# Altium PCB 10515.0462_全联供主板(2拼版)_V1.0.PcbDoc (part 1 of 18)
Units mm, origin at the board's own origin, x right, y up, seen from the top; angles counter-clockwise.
Board outline 282 x 198 mm, 2 copper layers (Top Layer, Bottom Layer); 716 components, 0 nets, 2364 pads, 1800 vias.
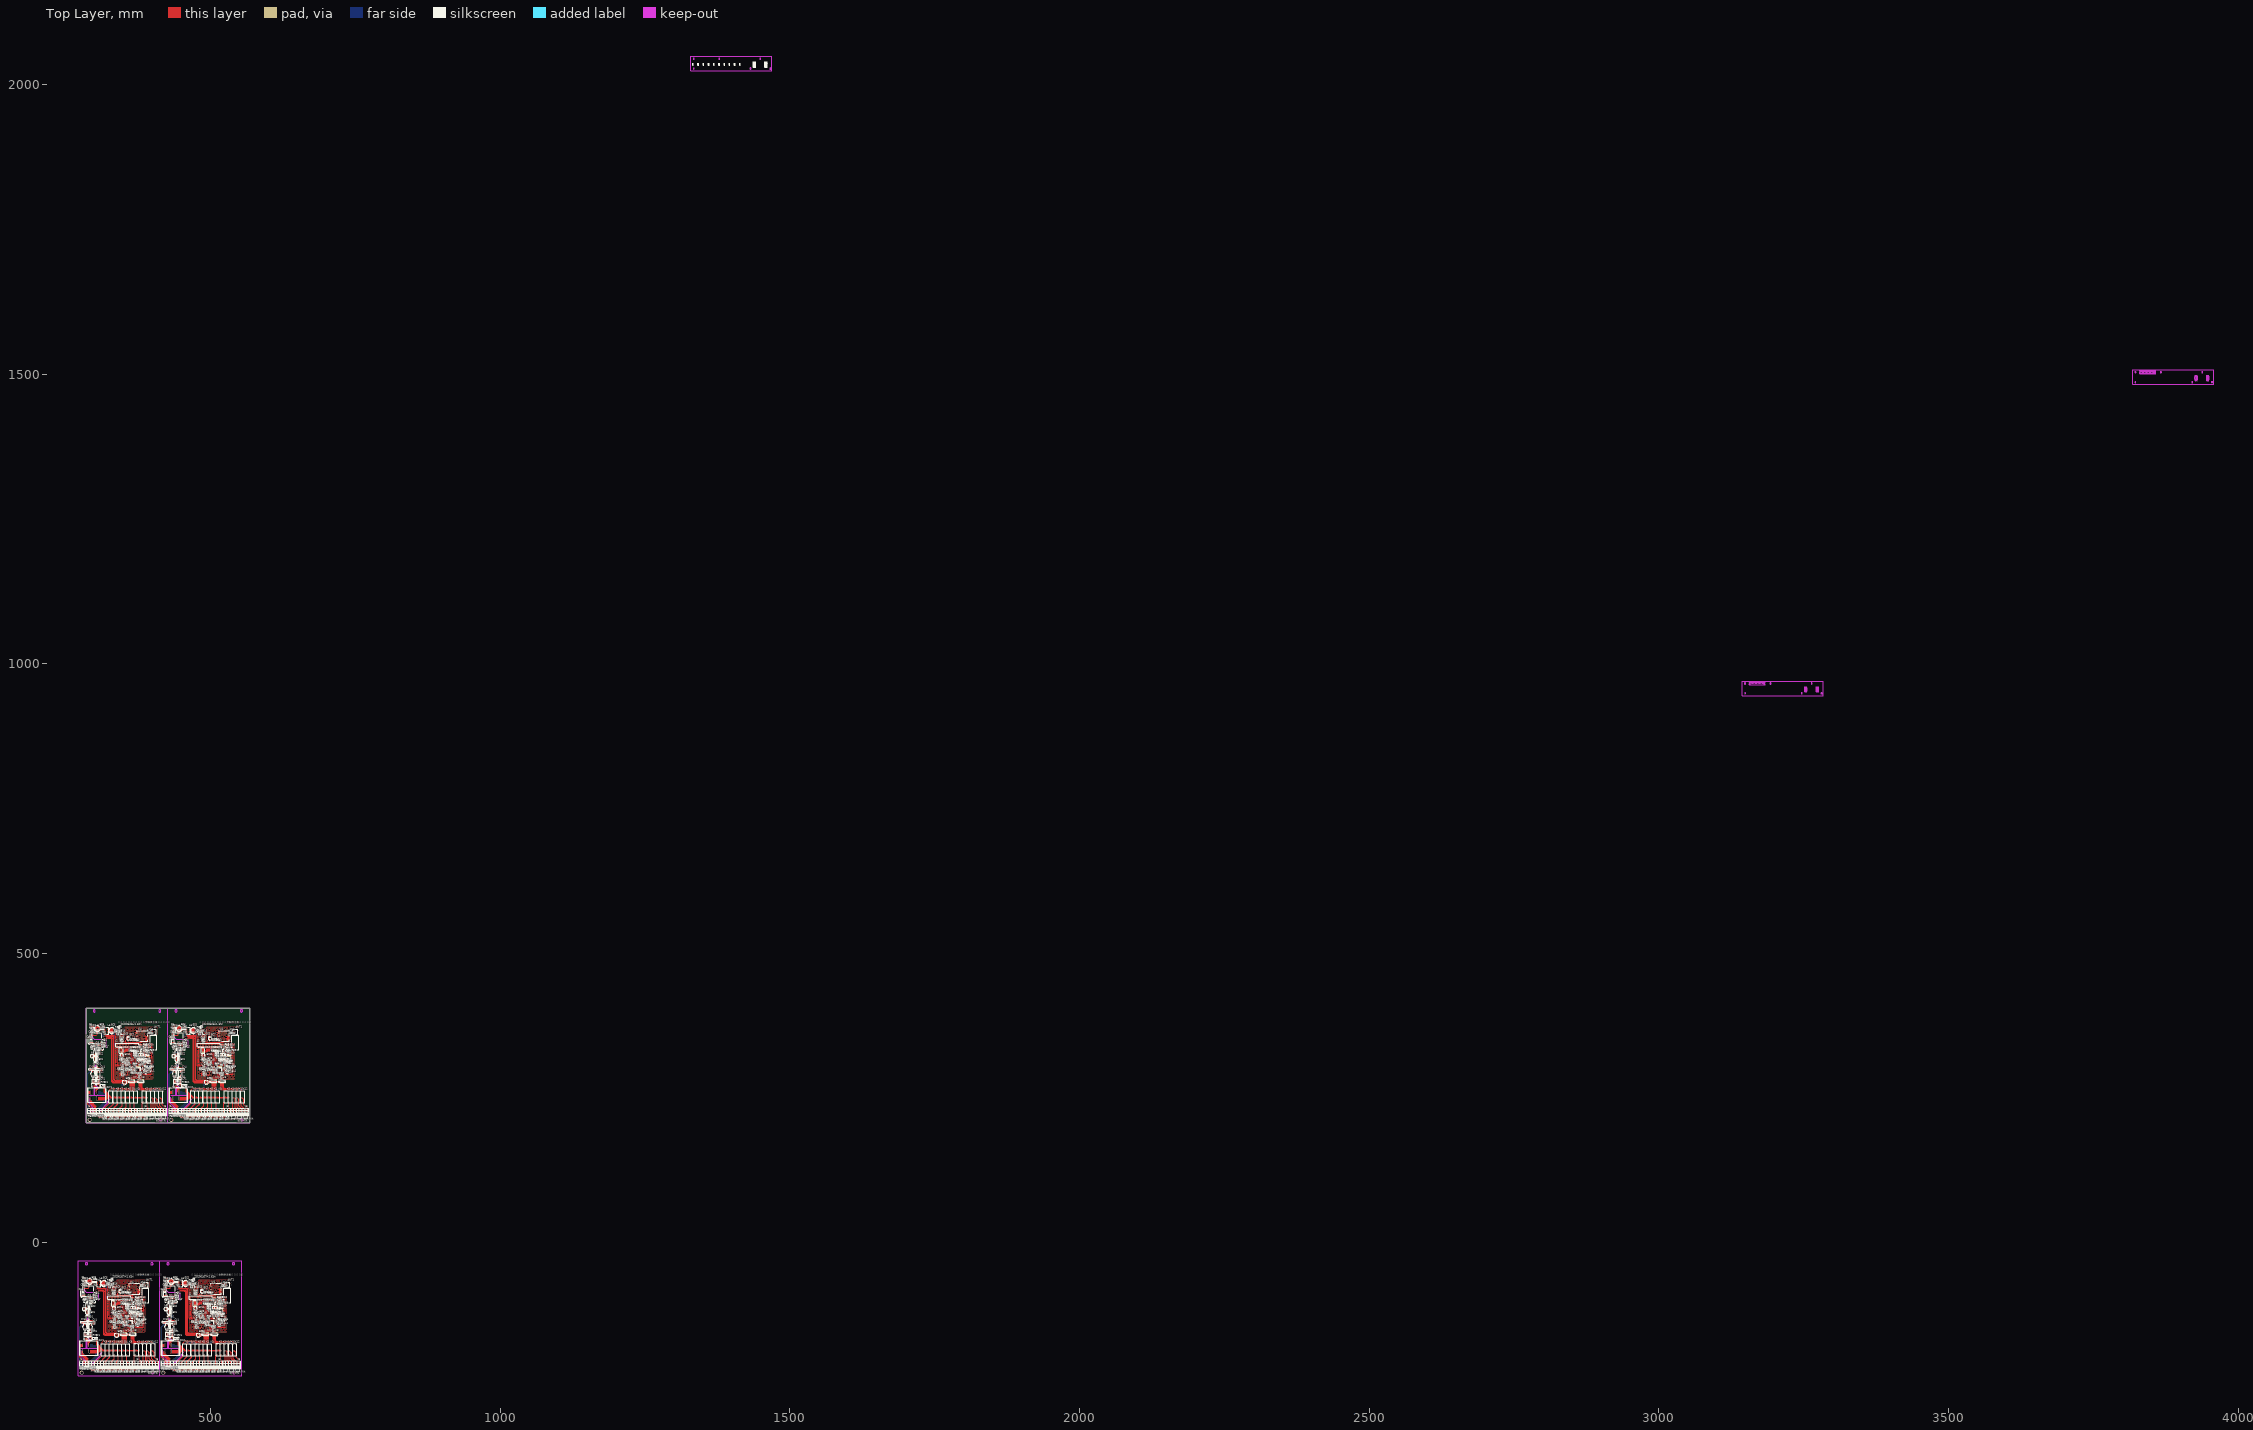
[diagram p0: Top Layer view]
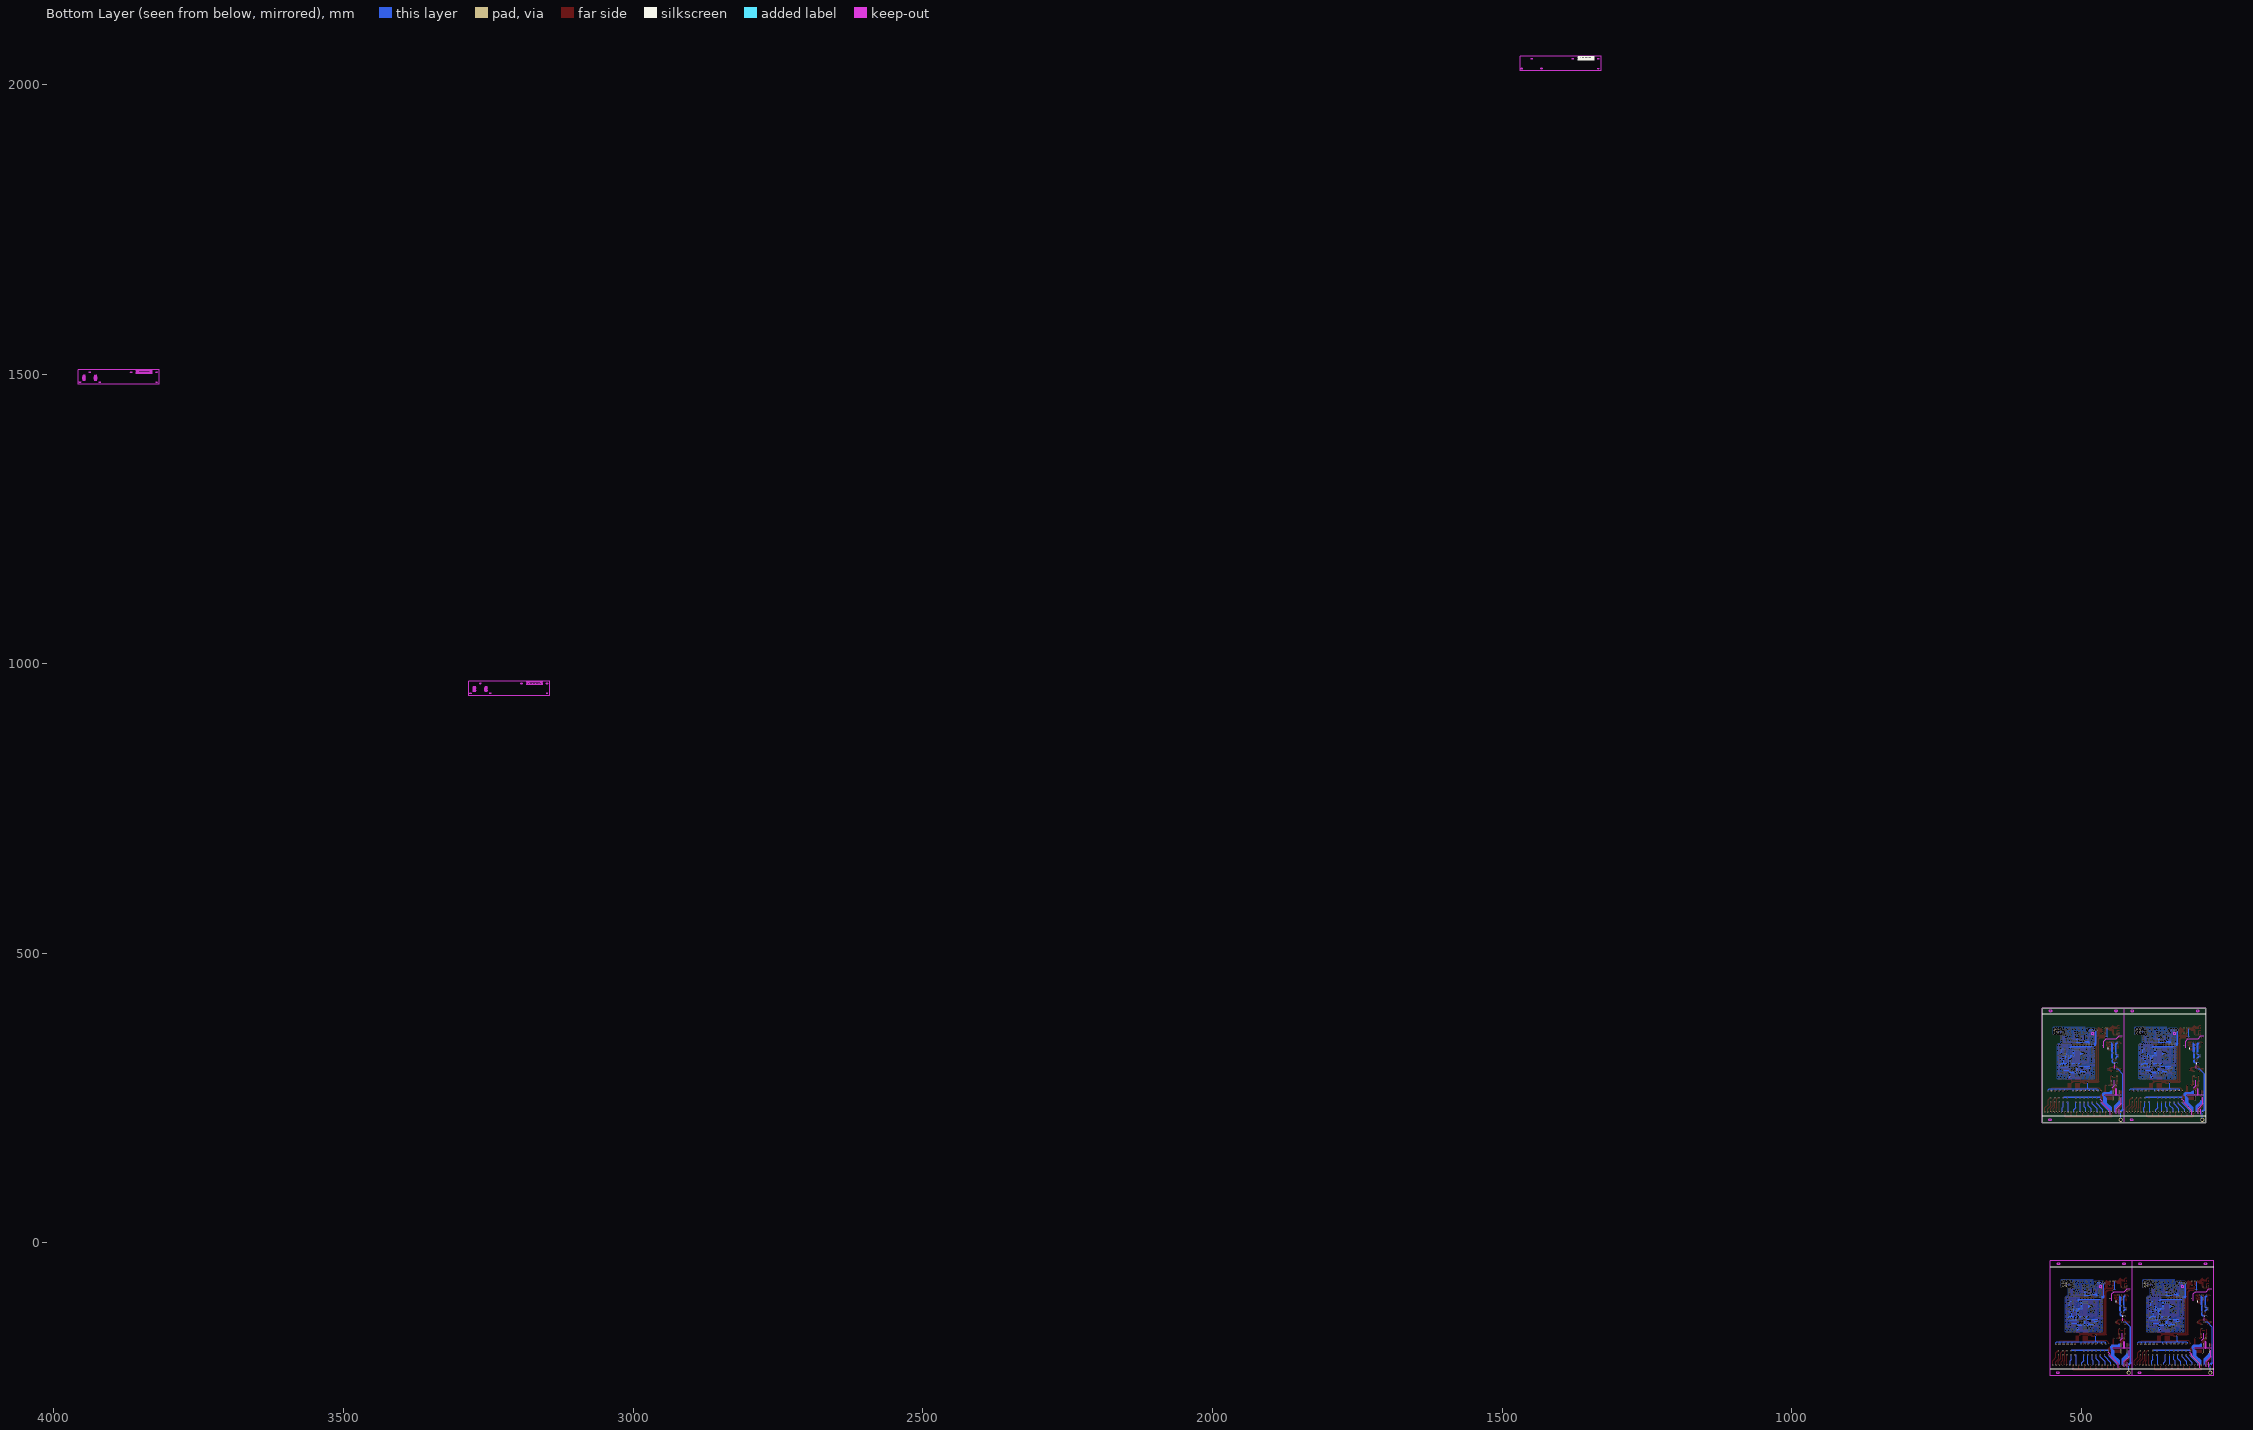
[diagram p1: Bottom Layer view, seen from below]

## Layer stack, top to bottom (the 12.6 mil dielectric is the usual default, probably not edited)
Top Layer: signal copper 0.0356
Dielectric: dielectric 0.32, FR-4, Dk 4.8
Bottom Layer: signal copper 0.0356

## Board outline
285.008,405.708 567.008,405.708 567.008,207.708 285.008,207.708 285.008,405.708

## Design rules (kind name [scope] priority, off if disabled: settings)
Clearance [All] p1: gap=0.254
PolygonConnect [All] p1: connectstyle=Relief reliefconductorwidth=0.254 reliefentries=4 polygonreliefangle="90 Angle"
RoutingVias [All] p1: holewidth=0.711 width=1.27 viastyle="Through Hole" minholewidth=0.711 minwidth=1.27 maxholewidth=0.711 maxwidth=1.27
SilkscreenOverComponentPads [All] p1: minsilkscreentomaskgap=0.254
SolderMaskExpansion [All] p1: expansion=0.102
Width [All] p1: maxlimit=0.254 minlimit=0.254 preferedwidth=0.254
27 further rules are at their usual default settings.

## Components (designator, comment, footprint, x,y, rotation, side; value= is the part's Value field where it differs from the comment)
+3.3V "OTHER/TEST" TEST#1 486.46,315.284 r90 top (schematic designator VCC1)
+3.3V "OTHER/TEST" TEST#1 345.46,315.284 r90 top (schematic designator VCC1)
+3.3V "OTHER/TEST" TEST#1 472.831,-121.311 r90 top (schematic designator VCC1)
+3.3V "OTHER/TEST" TEST#1 331.831,-121.311 r90 top (schematic designator VCC1)
ANT1 "SMA座" SMA 542.201,364.654 r180 top
ANT1 "SMA座" SMA 401.201,364.654 r180 top
ANT1 "SMA座" SMA 528.573,-71.942 r180 top
ANT1 "SMA座" SMA 387.573,-71.942 r180 top
C1 "1nF/630V" CAP/SMT/1206C 434.678,372.042 r90 top
C1 "1nF/630V" CAP/SMT/1206C 293.678,372.042 r90 top
C1 "1nF/630V" CAP/SMT/1206C 421.049,-64.553 r90 top
C1 "1nF/630V" CAP/SMT/1206C 280.049,-64.553 r90 top
C2 "1nF/630V" CAP/SMT/1206C 437.98,339.657 r90 top
C2 "1nF/630V" CAP/SMT/1206C 296.98,339.657 r90 top
C2 "1nF/630V" CAP/SMT/1206C 424.351,-96.938 r90 top
C2 "1nF/630V" CAP/SMT/1206C 283.351,-96.938 r90 top
C3 "1uF/0603" CAP/SMT/0603C 451.662,370.021 r270 top
C3 "1uF/0603" CAP/SMT/0603C 310.662,370.021 r270 top
C3 "1uF/0603" CAP/SMT/0603C 438.033,-66.574 r270 top
C3 "1uF/0603" CAP/SMT/0603C 297.033,-66.574 r270 top
C4 "0.1uF/0603" CAP/SMT/0603C 453.44,370.021 r270 top
C4 "0.1uF/0603" CAP/SMT/0603C 312.44,370.021 r270 top
C4 "0.1uF/0603" CAP/SMT/0603C 439.811,-66.574 r270 top
C4 "0.1uF/0603" CAP/SMT/0603C 298.811,-66.574 r270 top
C5 "0.1uF/0603" CAP/SMT/0603C 480.096,364.013 r180 top
C5 "0.1uF/0603" CAP/SMT/0603C 339.096,364.013 r180 top
C5 "0.1uF/0603" CAP/SMT/0603C 466.467,-72.582 r180 top
C5 "0.1uF/0603" CAP/SMT/0603C 325.467,-72.582 r180 top
C6 "0.1uF/0603" CAP/SMT/0603C 476.413,367.292 r270 top
C6 "0.1uF/0603" CAP/SMT/0603C 335.413,367.292 r270 top
C6 "0.1uF/0603" CAP/SMT/0603C 462.784,-69.303 r270 top
C6 "0.1uF/0603" CAP/SMT/0603C 321.784,-69.303 r270 top
C7 "0.1uF/0603" CAP/SMT/0603C 488.492,347.796 r180 top
C7 "0.1uF/0603" CAP/SMT/0603C 347.492,347.796 r180 top
C7 "0.1uF/0603" CAP/SMT/0603C 474.863,-88.799 r180 top
C7 "0.1uF/0603" CAP/SMT/0603C 333.863,-88.799 r180 top
C8 "1nF/0603" CAP/SMT/0603C 484.21,365.864 r90 top
C8 "1nF/0603" CAP/SMT/0603C 343.21,365.864 r90 top
C8 "1nF/0603" CAP/SMT/0603C 470.581,-70.731 r90 top
C8 "1nF/0603" CAP/SMT/0603C 329.581,-70.731 r90 top
C9 "10uF/0603" CAP/SMT/0603C 494.749,298.509 r90 top
C9 "10uF/0603" CAP/SMT/0603C 353.749,298.509 r90 top
C9 "10uF/0603" CAP/SMT/0603C 481.12,-138.086 r90 top
C9 "10uF/0603" CAP/SMT/0603C 340.12,-138.086 r90 top
C10 "0.1uF/0603" CAP/SMT/0603C 481.922,300.153 r90 top
C10 "0.1uF/0603" CAP/SMT/0603C 340.922,300.153 r90 top
C10 "0.1uF/0603" CAP/SMT/0603C 468.293,-136.442 r90 top
C10 "0.1uF/0603" CAP/SMT/0603C 327.293,-136.442 r90 top
C11 "0.1uF/0603" CAP/SMT/0603C 511.757,322.159 r180 top
C11 "0.1uF/0603" CAP/SMT/0603C 370.757,322.159 r180 top
C11 "0.1uF/0603" CAP/SMT/0603C 498.129,-114.437 r180 top
C11 "0.1uF/0603" CAP/SMT/0603C 357.128,-114.437 r180 top
C12 "1uF/0603" CAP/SMT/0603C 504.24,352.114 r270 top
C12 "1uF/0603" CAP/SMT/0603C 363.24,352.114 r270 top
C12 "1uF/0603" CAP/SMT/0603C 490.611,-84.481 r270 top
C12 "1uF/0603" CAP/SMT/0603C 349.611,-84.481 r270 top
C13 "0.1uF/0603" CAP/SMT/0603C 511.86,350.59 r90 top
C13 "0.1uF/0603" CAP/SMT/0603C 370.86,350.59 r90 top
C13 "0.1uF/0603" CAP/SMT/0603C 498.231,-86.005 r90 top
C13 "0.1uF/0603" CAP/SMT/0603C 357.231,-86.005 r90 top
C14 "0.1uF/0603" CAP/SMT/0603C 510.463,350.59 r90 top
C14 "0.1uF/0603" CAP/SMT/0603C 369.463,350.59 r90 top
C14 "0.1uF/0603" CAP/SMT/0603C 496.834,-86.005 r90 top
C14 "0.1uF/0603" CAP/SMT/0603C 355.834,-86.005 r90 top
C15 "1uF/0603" CAP/SMT/0603C 509.066,350.59 r90 top
C15 "1uF/0603" CAP/SMT/0603C 368.066,350.59 r90 top
C15 "1uF/0603" CAP/SMT/0603C 495.437,-86.005 r90 top
C15 "1uF/0603" CAP/SMT/0603C 354.437,-86.005 r90 top
C16 "0.1uF/0603" CAP/SMT/0603C 502.97,350.56 r90 top
C16 "0.1uF/0603" CAP/SMT/0603C 361.97,350.56 r90 top
C16 "0.1uF/0603" CAP/SMT/0603C 489.341,-86.036 r90 top
C16 "0.1uF/0603" CAP/SMT/0603C 348.341,-86.036 r90 top
C17 "NC" CAP/SMT/0603C 534.327,361.733 r90 top
C17 "NC" CAP/SMT/0603C 393.327,361.733 r90 top
C17 "NC" CAP/SMT/0603C 520.699,-74.863 r90 top
C17 "NC" CAP/SMT/0603C 379.699,-74.863 r90 top
C18 "NC" CAP/SMT/0603C 536.105,361.606 r90 top
C18 "NC" CAP/SMT/0603C 395.105,361.606 r90 top
C18 "NC" CAP/SMT/0603C 522.477,-74.99 r90 top
C18 "NC" CAP/SMT/0603C 381.477,-74.99 r90 top
C19 "0.1uF/0603" CAP/SMT/0603C 519.006,290.508 r0 top
C19 "0.1uF/0603" CAP/SMT/0603C 378.006,290.508 r0 top
C19 "0.1uF/0603" CAP/SMT/0603C 505.377,-146.087 r0 top
C19 "0.1uF/0603" CAP/SMT/0603C 364.377,-146.087 r0 top
C20 "0.1uF/0603" CAP/SMT/0603C 519.895,307.78 r180 top
C20 "0.1uF/0603" CAP/SMT/0603C 378.895,307.78 r180 top
C20 "0.1uF/0603" CAP/SMT/0603C 506.266,-128.815 r180 top
C20 "0.1uF/0603" CAP/SMT/0603C 365.266,-128.815 r180 top
C21 "0.1uF/0603" CAP/SMT/0603C 524.086,301.684 r90 top
C21 "0.1uF/0603" CAP/SMT/0603C 383.086,301.684 r90 top
C21 "0.1uF/0603" CAP/SMT/0603C 510.457,-134.911 r90 top
C21 "0.1uF/0603" CAP/SMT/0603C 369.457,-134.911 r90 top
C22 "0.1uF/0603" CAP/SMT/0603C 506.306,295.08 r270 top
C22 "0.1uF/0603" CAP/SMT/0603C 365.306,295.08 r270 top
C22 "0.1uF/0603" CAP/SMT/0603C 492.677,-141.515 r270 top
C22 "0.1uF/0603" CAP/SMT/0603C 351.677,-141.515 r270 top
C23 "0.1uF/0603" CAP/SMT/0603C 488.17,295.03 r0 top
C23 "0.1uF/0603" CAP/SMT/0603C 347.17,295.03 r0 top
C23 "0.1uF/0603" CAP/SMT/0603C 474.541,-141.565 r0 top
C23 "0.1uF/0603" CAP/SMT/0603C 333.541,-141.565 r0 top
C24 "0.1uF/0603" CAP/SMT/0603C 528.905,302.897 r0 top
C24 "0.1uF/0603" CAP/SMT/0603C 387.905,302.897 r0 top
C24 "0.1uF/0603" CAP/SMT/0603C 515.276,-133.698 r0 top
C24 "0.1uF/0603" CAP/SMT/0603C 374.276,-133.698 r0 top
C25 "20pF/0603" CAP/SMT/0603C 529.777,293.375 r180 top
C25 "20pF/0603" CAP/SMT/0603C 388.777,293.375 r180 top
C25 "20pF/0603" CAP/SMT/0603C 516.148,-143.22 r180 top
C25 "20pF/0603" CAP/SMT/0603C 375.148,-143.22 r180 top
C26 "20pF/0603" CAP/SMT/0603C 528.474,299.532 r0 top
C26 "20pF/0603" CAP/SMT/0603C 387.474,299.532 r0 top
C26 "20pF/0603" CAP/SMT/0603C 514.845,-137.063 r0 top
C26 "20pF/0603" CAP/SMT/0603C 373.845,-137.063 r0 top
C27 "0.1uF/0603" CAP/SMT/0603C 511.386,306.891 r180 top
C27 "0.1uF/0603" CAP/SMT/0603C 370.386,306.891 r180 top
C27 "0.1uF/0603" CAP/SMT/0603C 497.757,-129.704 r180 top
C27 "0.1uF/0603" CAP/SMT/0603C 356.757,-129.704 r180 top
C28 "0.1uF/0603" CAP/SMT/0603C 502.72,334.704 r180 top
C28 "0.1uF/0603" CAP/SMT/0603C 361.72,334.704 r180 top
C28 "0.1uF/0603" CAP/SMT/0603C 489.091,-101.891 r180 top
C28 "0.1uF/0603" CAP/SMT/0603C 348.091,-101.891 r180 top
C29 "0.1uF/0603" CAP/SMT/0603C 492.556,312.236 r270 top
C29 "0.1uF/0603" CAP/SMT/0603C 351.556,312.236 r270 top
C29 "0.1uF/0603" CAP/SMT/0603C 478.927,-124.359 r270 top
C29 "0.1uF/0603" CAP/SMT/0603C 337.927,-124.359 r270 top
C30 "0.1uF/0603" CAP/SMT/0603C 506.235,334.704 r180 top
C30 "0.1uF/0603" CAP/SMT/0603C 365.235,334.704 r180 top
C30 "0.1uF/0603" CAP/SMT/0603C 492.607,-101.891 r180 top
C30 "0.1uF/0603" CAP/SMT/0603C 351.607,-101.891 r180 top
C31 "0.1uF/0603" CAP/SMT/0603C 488.492,313.252 r180 top
C31 "0.1uF/0603" CAP/SMT/0603C 347.492,313.252 r180 top
C31 "0.1uF/0603" CAP/SMT/0603C 474.863,-123.343 r180 top
C31 "0.1uF/0603" CAP/SMT/0603C 333.863,-123.343 r180 top
C32 "0.1uF/0603" CAP/SMT/0603C 509.705,334.704 r180 top
C32 "0.1uF/0603" CAP/SMT/0603C 368.705,334.704 r180 top
C32 "0.1uF/0603" CAP/SMT/0603C 496.076,-101.891 r180 top
C32 "0.1uF/0603" CAP/SMT/0603C 355.076,-101.891 r180 top
C34 "51pF" CAP/SMT/0603C 513.783,323.742 r0 top
C34 "51pF" CAP/SMT/0603C 372.783,323.742 r0 top
C34 "51pF" CAP/SMT/0603C 500.154,-112.853 r0 top
C34 "51pF" CAP/SMT/0603C 359.154,-112.853 r0 top
C35 "0.1uF/0603" CAP/SMT/0603C 499.067,279.586 r270 top
C35 "0.1uF/0603" CAP/SMT/0603C 358.067,279.586 r270 top
C35 "0.1uF/0603" CAP/SMT/0603C 485.438,-157.009 r270 top
C35 "0.1uF/0603" CAP/SMT/0603C 344.438,-157.009 r270 top
C36 "0.1uF/0603" CAP/SMT/0603C 514.561,279.586 r270 top
C36 "0.1uF/0603" CAP/SMT/0603C 373.561,279.586 r270 top
C36 "0.1uF/0603" CAP/SMT/0603C 500.932,-157.009 r270 top
C36 "0.1uF/0603" CAP/SMT/0603C 359.932,-157.009 r270 top
C37 "0.1uF/0603" CAP/SMT/0603C 529.132,324.564 r90 top
C37 "0.1uF/0603" CAP/SMT/0603C 388.132,324.564 r90 top
C37 "0.1uF/0603" CAP/SMT/0603C 515.503,-112.032 r90 top
C37 "0.1uF/0603" CAP/SMT/0603C 374.503,-112.032 r90 top
C40 "1uF/0603" CAP/SMT/0603C 500.557,312.236 r270 top
C40 "1uF/0603" CAP/SMT/0603C 359.557,312.236 r270 top
C40 "1uF/0603" CAP/SMT/0603C 486.928,-124.359 r270 top
C40 "1uF/0603" CAP/SMT/0603C 345.928,-124.359 r270 top
C42 "22uF/0805" CAP/SMT/0805C 489,349.828 r180 top
C42 "22uF/0805" CAP/SMT/0805C 348,349.828 r180 top
C42 "22uF/0805" CAP/SMT/0805C 475.371,-86.767 r180 top
C42 "22uF/0805" CAP/SMT/0805C 334.371,-86.767 r180 top
C43 "22uF/0805" CAP/SMT/0805C 489,352.368 r180 top
C43 "22uF/0805" CAP/SMT/0805C 348,352.368 r180 top
C43 "22uF/0805" CAP/SMT/0805C 475.371,-84.227 r180 top
C43 "22uF/0805" CAP/SMT/0805C 334.371,-84.227 r180 top
C44 "0.1uF/0603" CAP/SMT/0603C 488.492,346.272 r180 top
C44 "0.1uF/0603" CAP/SMT/0603C 347.492,346.272 r180 top
C44 "0.1uF/0603" CAP/SMT/0603C 474.863,-90.323 r180 top
C44 "0.1uF/0603" CAP/SMT/0603C 333.863,-90.323 r180 top
C45 "0.1uF/0603" CAP/SMT/0603C 511.352,308.299 r180 top
C45 "0.1uF/0603" CAP/SMT/0603C 370.352,308.299 r180 top
C45 "0.1uF/0603" CAP/SMT/0603C 497.723,-128.296 r180 top
C45 "0.1uF/0603" CAP/SMT/0603C 356.723,-128.296 r180 top
C46 "0.1uF/0603" CAP/SMT/0603C 488.492,317.316 r180 top
C46 "0.1uF/0603" CAP/SMT/0603C 347.492,317.316 r180 top
C46 "0.1uF/0603" CAP/SMT/0603C 474.863,-119.279 r180 top
C46 "0.1uF/0603" CAP/SMT/0603C 333.863,-119.279 r180 top
C48 "0.1uF/0603" CAP/SMT/0603C 488.145,305.621 r0 top
C48 "0.1uF/0603" CAP/SMT/0603C 347.145,305.621 r0 top
C48 "0.1uF/0603" CAP/SMT/0603C 474.516,-130.974 r0 top
C48 "0.1uF/0603" CAP/SMT/0603C 333.516,-130.974 r0 top
C49 "10uF/0603" CAP/SMT/0603C 499.321,298.509 r90 top
C49 "10uF/0603" CAP/SMT/0603C 358.321,298.509 r90 top
C49 "10uF/0603" CAP/SMT/0603C 485.692,-138.086 r90 top
C49 "10uF/0603" CAP/SMT/0603C 344.692,-138.086 r90 top
CX1 "NC" CAP/DIP/0.1uF/250V 438.2,279.724 r180 top
CX1 "NC" CAP/DIP/0.1uF/250V 297.2,279.724 r180 top
CX1 "NC" CAP/DIP/0.1uF/250V 424.571,-156.871 r180 top
CX1 "NC" CAP/DIP/0.1uF/250V 283.571,-156.871 r180 top
CY1 "222M/250V" CAP/DIP/102M/250V 431.249,344.61 r90 top
CY1 "222M/250V" CAP/DIP/102M/250V 290.249,344.61 r90 top
CY1 "222M/250V" CAP/DIP/102M/250V 417.62,-91.985 r90 top
CY1 "222M/250V" CAP/DIP/102M/250V 276.62,-91.985 r90 top
CY2 "222M/250V" CAP/DIP/102M/250V 434.678,352.611 r90 top
CY2 "222M/250V" CAP/DIP/102M/250V 293.678,352.611 r90 top
CY2 "222M/250V" CAP/DIP/102M/250V 421.049,-83.984 r90 top
CY2 "222M/250V" CAP/DIP/102M/250V 280.049,-83.984 r90 top
CY3 "NC" CAP/DIP/102M/250V 440.74,300.044 r180 top
CY3 "NC" CAP/DIP/102M/250V 299.74,300.044 r180 top
CY3 "NC" CAP/DIP/102M/250V 427.111,-136.551 r180 top
CY3 "NC" CAP/DIP/102M/250V 286.111,-136.551 r180 top
CY4 "NC" CAP/DIP/102M/250V 453.948,300.044 r180 top
CY4 "NC" CAP/DIP/102M/250V 312.948,300.044 r180 top
CY4 "NC" CAP/DIP/102M/250V 440.319,-136.551 r180 top
CY4 "NC" CAP/DIP/102M/250V 299.319,-136.551 r180 top
D1 "MB10S" D/SMT/MD6S-TR 442.298,307.653 r90 top
D1 "MB10S" D/SMT/MD6S-TR 301.298,307.653 r90 top
D1 "MB10S" D/SMT/MD6S-TR 428.669,-128.942 r90 top
D1 "MB10S" D/SMT/MD6S-TR 287.669,-128.942 r90 top
D2 "SS210" D/SMT/DO-214AC 438.234,366.073 r270 top
D2 "SS210" D/SMT/DO-214AC 297.234,366.073 r270 top
D2 "SS210" D/SMT/DO-214AC 424.605,-70.522 r270 top
D2 "SS210" D/SMT/DO-214AC 283.605,-70.522 r270 top
D3 "1N4007-SOD123" D/SMT/SOD123 440.647,338.514 r90 top
D3 "1N4007-SOD123" D/SMT/SOD123 299.647,338.514 r90 top
D3 "1N4007-SOD123" D/SMT/SOD123 427.018,-98.081 r90 top
D3 "1N4007-SOD123" D/SMT/SOD123 286.018,-98.081 r90 top
D4 "F7" D/SMT/DO-214AC 456.996,346.272 r90 top
D4 "F7" D/SMT/DO-214AC 315.996,346.272 r90 top
D4 "F7" D/SMT/DO-214AC 443.367,-90.323 r90 top
D4 "F7" D/SMT/DO-214AC 302.367,-90.323 r90 top
D5 "1N4148/SOD-123" D/SMT/SOD-123 534.112,302.897 r180 top
D5 "1N4148/SOD-123" D/SMT/SOD-123 393.112,302.897 r180 top
D5 "1N4148/SOD-123" D/SMT/SOD-123 520.483,-133.698 r180 top
D5 "1N4148/SOD-123" D/SMT/SOD-123 379.483,-133.698 r180 top
D6 "SMAJ13CA" D/SMT/SMBJ4.0A 513.892,333.191 r0 top
D6 "SMAJ13CA" D/SMT/SMBJ4.0A 372.892,333.191 r0 top
D6 "SMAJ13CA" D/SMT/SMBJ4.0A 500.263,-103.404 r0 top
D6 "SMAJ13CA" D/SMT/SMBJ4.0A 359.263,-103.404 r0 top
D9 "SMBJ6.5A/SOCAY" D/SMT/SMBJ4.0A 529.64,333.572 r90 top
D9 "SMBJ6.5A/SOCAY" D/SMT/SMBJ4.0A 388.64,333.572 r90 top
D9 "SMBJ6.5A/SOCAY" D/SMT/SMBJ4.0A 516.011,-103.023 r90 top
D9 "SMBJ6.5A/SOCAY" D/SMT/SMBJ4.0A 375.011,-103.023 r90 top
D10 "SMBJ6.5A/SOCAY" D/SMT/SMBJ4.0A 534.466,333.572 r90 top
D10 "SMBJ6.5A/SOCAY" D/SMT/SMBJ4.0A 393.466,333.572 r90 top
D10 "SMBJ6.5A/SOCAY" D/SMT/SMBJ4.0A 520.837,-103.023 r90 top
D10 "SMBJ6.5A/SOCAY" D/SMT/SMBJ4.0A 379.837,-103.023 r90 top
EC1 "8.2uF/400V" CAP/DIP/6.8UF/400V/10MM 442.806,317.686 r270 top
EC1 "8.2uF/400V" CAP/DIP/6.8UF/400V/10MM 301.806,317.686 r270 top
EC1 "8.2uF/400V" CAP/DIP/6.8UF/400V/10MM 429.177,-118.909 r270 top
EC1 "8.2uF/400V" CAP/DIP/6.8UF/400V/10MM 288.177,-118.909 r270 top
EC2 "8.2uF/400V" CAP/DIP/6.8UF/400V/10MM 442.806,327.973 r270 top
EC2 "8.2uF/400V" CAP/DIP/6.8UF/400V/10MM 301.806,327.973 r270 top
EC2 "8.2uF/400V" CAP/DIP/6.8UF/400V/10MM 429.177,-108.622 r270 top
EC2 "8.2uF/400V" CAP/DIP/6.8UF/400V/10MM 288.177,-108.622 r270 top
EC3 "330uF/50V" CAP/SMT/220UF/50V 450.519,375.228 r270 top
EC3 "330uF/50V" CAP/SMT/220UF/50V 309.519,375.228 r270 top
EC3 "330uF/50V" CAP/SMT/220UF/50V 436.89,-61.367 r270 top
EC3 "330uF/50V" CAP/SMT/220UF/50V 295.89,-61.367 r270 top
EC4 "10uF/50V" CAP/DIP/10uF/50V 453.855,336.609 r270 top
EC4 "10uF/50V" CAP/DIP/10uF/50V 312.855,336.609 r270 top
EC4 "10uF/50V" CAP/DIP/10uF/50V 440.226,-99.986 r270 top
EC4 "10uF/50V" CAP/DIP/10uF/50V 299.226,-99.986 r270 top
EC5 "220uF/50V" CAP/SMT/220UF/50V 475.284,371.672 r270 top
EC5 "220uF/50V" CAP/SMT/220UF/50V 334.284,371.672 r270 top
EC5 "220uF/50V" CAP/SMT/220UF/50V 461.655,-64.923 r270 top
EC5 "220uF/50V" CAP/SMT/220UF/50V 320.655,-64.923 r270 top
EC6 "220uF/16V" CAP/SMT/220UF/16V 487.476,357.448 r0 top
EC6 "220uF/16V" CAP/SMT/220UF/16V 346.476,357.448 r0 top
EC6 "220uF/16V" CAP/SMT/220UF/16V 473.847,-79.147 r0 top
EC6 "220uF/16V" CAP/SMT/220UF/16V 332.847,-79.147 r0 top
EC7 "330uF/6.3V" CAP/SMT/330UF/6.3V 498.652,349.828 r90 top
EC7 "330uF/6.3V" CAP/SMT/330UF/6.3V 357.652,349.828 r90 top
EC7 "330uF/6.3V" CAP/SMT/330UF/6.3V 485.023,-86.767 r90 top
EC7 "330uF/6.3V" CAP/SMT/330UF/6.3V 344.023,-86.767 r90 top
EC8 "100uF/50V" CAP/SMT/220UF/16V 492.556,277.438 r90 top
EC8 "100uF/50V" CAP/SMT/220UF/16V 351.556,277.438 r90 top
EC8 "100uF/50V" CAP/SMT/220UF/16V 478.927,-159.157 r90 top
EC8 "100uF/50V" CAP/SMT/220UF/16V 337.927,-159.157 r90 top
EC9 "TEC/47uF/10V" CAP/SMT/TAJC476M010RNJ 496.62,308.68 r90 top
EC9 "TEC/47uF/10V" CAP/SMT/TAJC476M010RNJ 355.62,308.68 r90 top
EC9 "TEC/47uF/10V" CAP/SMT/TAJC476M010RNJ 482.991,-127.915 r90 top
EC9 "TEC/47uF/10V" CAP/SMT/TAJC476M010RNJ 341.991,-127.915 r90 top
EC11 "100uF/25V" CAP/SMT/100UF/25V 484.428,323.92 r0 top
EC11 "100uF/25V" CAP/SMT/100UF/25V 343.428,323.92 r0 top
EC11 "100uF/25V" CAP/SMT/100UF/25V 470.799,-112.675 r0 top
EC11 "100uF/25V" CAP/SMT/100UF/25V 329.799,-112.675 r0 top
GND1 "OTHER/TEST" TEST#1 490.524,312.262 r270 top
GND1 "OTHER/TEST" TEST#1 349.524,312.262 r270 top
GND1 "OTHER/TEST" TEST#1 476.895,-124.334 r270 top
GND1 "OTHER/TEST" TEST#1 335.895,-124.334 r270 top
J1 "WJ103-5.0" CON/DIP/1×3PIN/5.0MM/WJ103-3P 436.71,225.611 r180 top
J1 "WJ103-5.0" CON/DIP/1×3PIN/5.0MM/WJ103-3P 295.71,225.611 r180 top
J1 "WJ103-5.0" CON/DIP/1×3PIN/5.0MM/WJ103-3P 423.081,-210.984 r180 top
J1 "WJ103-5.0" CON/DIP/1×3PIN/5.0MM/WJ103-3P 282.081,-210.984 r180 top
J2 "CON/DIP/2X15PIN" CON/DIP/2X15PIN/2.54MM 479.21,340.8 r90 top
J2 "CON/DIP/2X15PIN" CON/DIP/2X15PIN/2.54MM 338.21,340.8 r90 top
J2 "CON/DIP/2X15PIN" CON/DIP/2X15PIN/2.54MM 465.581,-95.795 r90 top
J2 "CON/DIP/2X15PIN" CON/DIP/2X15PIN/2.54MM 324.581,-95.795 r90 top
J3 "1X5PIN_2MM" CON/DIP/1×5PIN/2.0MM 536.144,305.437 r180 top
J3 "1X5PIN_2MM" CON/DIP/1×5PIN/2.0MM 395.144,305.437 r180 top
J3 "1X5PIN_2MM" CON/DIP/1×5PIN/2.0MM 522.515,-131.158 r180 top
J3 "1X5PIN_2MM" CON/DIP/1×5PIN/2.0MM 381.515,-131.158 r180 top
J6 "WJ103-5.0" CON/DIP/1×18PIN/5.0MM/WJ103-18P 492.59,225.611 r180 top
J6 "WJ103-5.0" CON/DIP/1×18PIN/5.0MM/WJ103-18P 351.59,225.611 r180 top
J6 "WJ103-5.0" CON/DIP/1×18PIN/5.0MM/WJ103-18P 478.961,-210.984 r180 top
J6 "WJ103-5.0" CON/DIP/1×18PIN/5.0MM/WJ103-18P 337.961,-210.984 r180 top
J8 "WJ103-5.0" CON/DIP/1×6PIN/5.0MM/WJ103-6P 550.092,225.611 r180 top
J8 "WJ103-5.0" CON/DIP/1×6PIN/5.0MM/WJ103-6P 409.092,225.611 r180 top
J8 "WJ103-5.0" CON/DIP/1×6PIN/5.0MM/WJ103-6P 536.463,-210.984 r180 top
J8 "WJ103-5.0" CON/DIP/1×6PIN/5.0MM/WJ103-6P 395.463,-210.984 r180 top
K1 "HF46F/024-HS1T" RELAY/HF46F-012-HSIT 535.897,261.97 r0 top
K1 "HF46F/024-HS1T" RELAY/HF46F-012-HSIT 394.897,261.97 r0 top
K1 "HF46F/024-HS1T" RELAY/HF46F-012-HSIT 522.268,-174.625 r0 top
K1 "HF46F/024-HS1T" RELAY/HF46F-012-HSIT 381.268,-174.625 r0 top
K2 "HF46F/024-HS1T" RELAY/HF46F-012-HSIT 528.785,261.97 r0 top
K2 "HF46F/024-HS1T" RELAY/HF46F-012-HSIT 387.785,261.97 r0 top
K2 "HF46F/024-HS1T" RELAY/HF46F-012-HSIT 515.156,-174.625 r0 top
K2 "HF46F/024-HS1T" RELAY/HF46F-012-HSIT 374.156,-174.625 r0 top
K3 "HF46F/024-HS1T" RELAY/HF46F-012-HSIT 513.926,261.843 r0 top
K3 "HF46F/024-HS1T" RELAY/HF46F-012-HSIT 372.926,261.843 r0 top
K3 "HF46F/024-HS1T" RELAY/HF46F-012-HSIT 500.297,-174.752 r0 top
K3 "HF46F/024-HS1T" RELAY/HF46F-012-HSIT 359.297,-174.752 r0 top
K4 "HF46F/024-HS1T" RELAY/HF46F-012-HSIT 506.824,261.843 r0 top
K4 "HF46F/024-HS1T" RELAY/HF46F-012-HSIT 365.823,261.843 r0 top
K4 "HF46F/024-HS1T" RELAY/HF46F-012-HSIT 493.195,-174.752 r0 top
K4 "HF46F/024-HS1T" RELAY/HF46F-012-HSIT 352.195,-174.752 r0 top
K5 "HF46F/024-HS1T" RELAY/HF46F-012-HSIT 499.664,261.843 r0 top
K5 "HF46F/024-HS1T" RELAY/HF46F-012-HSIT 358.664,261.843 r0 top
K5 "HF46F/024-HS1T" RELAY/HF46F-012-HSIT 486.035,-174.752 r0 top
K5 "HF46F/024-HS1T" RELAY/HF46F-012-HSIT 345.035,-174.752 r0 top
K6 "HF46F/024-HS1T" RELAY/HF46F-012-HSIT 492.504,261.843 r0 top
K6 "HF46F/024-HS1T" RELAY/HF46F-012-HSIT 351.504,261.843 r0 top
K6 "HF46F/024-HS1T" RELAY/HF46F-012-HSIT 478.875,-174.752 r0 top
K6 "HF46F/024-HS1T" RELAY/HF46F-012-HSIT 337.875,-174.752 r0 top
K7 "HF46F/024-HS1T" RELAY/HF46F-012-HSIT 485.345,261.843 r0 top
K7 "HF46F/024-HS1T" RELAY/HF46F-012-HSIT 344.345,261.843 r0 top
K7 "HF46F/024-HS1T" RELAY/HF46F-012-HSIT 471.716,-174.752 r0 top
K7 "HF46F/024-HS1T" RELAY/HF46F-012-HSIT 330.716,-174.752 r0 top
K8 "HF46F/024-HS1T" RELAY/HF46F-012-HSIT 478.185,261.843 r0 top
K8 "HF46F/024-HS1T" RELAY/HF46F-012-HSIT 337.185,261.843 r0 top
K8 "HF46F/024-HS1T" RELAY/HF46F-012-HSIT 464.556,-174.752 r0 top
K8 "HF46F/024-HS1T" RELAY/HF46F-012-HSIT 323.556,-174.752 r0 top
K9 "HF46F/024-HS1T" RELAY/HF46F-012-HSIT 471,261.843 r0 top
K9 "HF46F/024-HS1T" RELAY/HF46F-012-HSIT 330,261.843 r0 top
K9 "HF46F/024-HS1T" RELAY/HF46F-012-HSIT 457.371,-174.752 r0 top
K9 "HF46F/024-HS1T" RELAY/HF46F-012-HSIT 316.371,-174.752 r0 top
K10 "HF46F/024-HS1T" RELAY/HF46F-012-HSIT 543.016,261.97 r0 top
K10 "HF46F/024-HS1T" RELAY/HF46F-012-HSIT 402.016,261.97 r0 top
K10 "HF46F/024-HS1T" RELAY/HF46F-012-HSIT 529.387,-174.625 r0 top
K10 "HF46F/024-HS1T" RELAY/HF46F-012-HSIT 388.387,-174.625 r0 top
K11 "HF46F/024-HS1T" RELAY/HF46F-012-HSIT 550.128,261.97 r0 top
K11 "HF46F/024-HS1T" RELAY/HF46F-012-HSIT 409.128,261.97 r0 top
K11 "HF46F/024-HS1T" RELAY/HF46F-012-HSIT 536.499,-174.625 r0 top
K11 "HF46F/024-HS1T" RELAY/HF46F-012-HSIT 395.499,-174.625 r0 top
K12 "HF46F/024-HS1T" RELAY/HF46F-012-HSIT 557.367,261.97 r0 top
K12 "HF46F/024-HS1T" RELAY/HF46F-012-HSIT 416.367,261.97 r0 top
K12 "HF46F/024-HS1T" RELAY/HF46F-012-HSIT 543.738,-174.625 r0 top
K12 "HF46F/024-HS1T" RELAY/HF46F-012-HSIT 402.738,-174.625 r0 top
L1 "1mH" L/DIP/1mH 435.821,321.242 r90 top
L1 "1mH" L/DIP/1mH 294.821,321.242 r90 top
L1 "1mH" L/DIP/1mH 422.192,-115.353 r90 top
L1 "1mH" L/DIP/1mH 281.192,-115.353 r90 top
L2 "20mH/UU9.8" L/DIP/20mH/UU9.8 446.328,288.868 r180 top
L2 "20mH/UU9.8" L/DIP/20mH/UU9.8 305.328,288.868 r180 top
L2 "20mH/UU9.8" L/DIP/20mH/UU9.8 432.699,-147.727 r180 top
L2 "20mH/UU9.8" L/DIP/20mH/UU9.8 291.699,-147.727 r180 top
L3 "10UH" L/SMT/SWPA3015S150MT 478.953,361.069 r0 top
L3 "10UH" L/SMT/SWPA3015S150MT 337.953,361.069 r0 top
L3 "10UH" L/SMT/SWPA3015S150MT 465.324,-75.526 r0 top
L3 "10UH" L/SMT/SWPA3015S150MT 324.324,-75.526 r0 top
L4 "L/10uH" L/SMT/0603L 507.415,350.59 r180 top
L4 "L/10uH" L/SMT/0603L 366.415,350.59 r180 top
L4 "L/10uH" L/SMT/0603L 493.786,-86.005 r180 top
L4 "L/10uH" L/SMT/0603L 352.786,-86.005 r180 top
L5 "100uH_共模电感" L/DIP/500uH 463.6,370.656 r270 top
L5 "100uH_共模电感" L/DIP/500uH 322.6,370.656 r270 top
L5 "100uH_共模电感" L/DIP/500uH 449.971,-65.939 r270 top
L5 "100uH_共模电感" L/DIP/500uH 308.971,-65.939 r270 top
LED1 "BL-HG635A-TRB高亮绿" D/SMT/LED/0805 524.56,313.252 r270 top
LED1 "BL-HG635A-TRB高亮绿" D/SMT/LED/0805 383.56,313.252 r270 top
LED1 "BL-HG635A-TRB高亮绿" D/SMT/LED/0805 510.931,-123.343 r270 top
LED1 "BL-HG635A-TRB高亮绿" D/SMT/LED/0805 369.931,-123.343 r270 top
Q1 "BC807" BJT/SMT/SOT-23 523.798,333.699 r180 top
Q1 "BC807" BJT/SMT/SOT-23 382.798,333.699 r180 top
Q1 "BC807" BJT/SMT/SOT-23 510.169,-102.896 r180 top
Q1 "BC807" BJT/SMT/SOT-23 369.169,-102.896 r180 top
Q2 "NPN_SS8050" BJT/SMT/SOT-23 521.673,324.036 r0 top
Q2 "NPN_SS8050" BJT/SMT/SOT-23 380.673,324.036 r0 top
Q2 "NPN_SS8050" BJT/SMT/SOT-23 508.044,-112.559 r0 top
Q2 "NPN_SS8050" BJT/SMT/SOT-23 367.044,-112.559 r0 top
Q3 "NPN_SS8050" BJT/SMT/SOT-23 521.673,319.464 r0 top
Q3 "NPN_SS8050" BJT/SMT/SOT-23 380.673,319.464 r0 top
Q3 "NPN_SS8050" BJT/SMT/SOT-23 508.044,-117.131 r0 top
Q3 "NPN_SS8050" BJT/SMT/SOT-23 367.044,-117.131 r0 top
Q4 "NPN_SS8050" BJT/SMT/SOT-23 517.482,324.036 r0 top
Q4 "NPN_SS8050" BJT/SMT/SOT-23 376.482,324.036 r0 top
Q4 "NPN_SS8050" BJT/SMT/SOT-23 503.853,-112.559 r0 top
Q4 "NPN_SS8050" BJT/SMT/SOT-23 362.853,-112.559 r0 top
Q5 "NPN_SS8050" BJT/SMT/SOT-23 515.577,322.004 r180 top
Q5 "NPN_SS8050" BJT/SMT/SOT-23 374.577,322.004 r180 top
Q5 "NPN_SS8050" BJT/SMT/SOT-23 501.948,-114.591 r180 top
Q5 "NPN_SS8050" BJT/SMT/SOT-23 360.948,-114.591 r180 top
R1 "47R/1206" 1206R 434.678,366.073 r90 top
R1 "47R/1206" 1206R 293.678,366.073 r90 top
R1 "47R/1206" 1206R 421.049,-70.522 r90 top
R1 "47R/1206" 1206R 280.049,-70.522 r90 top
R2 "NC" 1206R 438.219,284.931 r0 top
R2 "NC" 1206R 297.219,284.931 r0 top
R2 "NC" 1206R 424.591,-151.664 r0 top
R2 "NC" 1206R 283.591,-151.664 r0 top
R3 "180K/5%/1206" 1206R 435.186,339.657 r90 top
R3 "180K/5%/1206" 1206R 294.186,339.657 r90 top
R3 "180K/5%/1206" 1206R 421.557,-96.938 r90 top
R3 "180K/5%/1206" 1206R 280.557,-96.938 r90 top
R4 "NC" 1206R 445.331,284.931 r0 top
R4 "NC" 1206R 304.331,284.931 r0 top
R4 "NC" 1206R 431.703,-151.664 r0 top
R4 "NC" 1206R 290.703,-151.664 r0 top
R5 "6.8K/0603" 0603R 455.218,369.259 r90 top
R5 "6.8K/0603" 0603R 314.218,369.259 r90 top
R5 "6.8K/0603" 0603R 441.589,-67.336 r90 top
R5 "6.8K/0603" 0603R 300.589,-67.336 r90 top
R6 "100R/1206" 1206R 439.758,335.593 r180 top
R6 "100R/1206" 1206R 298.758,335.593 r180 top
R6 "100R/1206" 1206R 426.129,-101.002 r180 top
R6 "100R/1206" 1206R 285.129,-101.002 r180 top
R7 "10R/0805" 0805R 454.109,339.276 r90 top
R7 "10R/0805" 0805R 313.109,339.276 r90 top
R7 "10R/0805" 0805R 440.48,-97.319 r90 top
R7 "10R/0805" 0805R 299.48,-97.319 r90 top
R8 "20K/0805" 0805R 454.109,343.848 r90 top
R8 "20K/0805" 0805R 313.109,343.848 r90 top
R8 "20K/0805" 0805R 440.48,-92.747 r90 top
R8 "20K/0805" 0805R 299.48,-92.747 r90 top
R9 "3.6K/0805" 0805R 447.632,334.196 r90 top
R9 "3.6K/0805" 0805R 306.632,334.196 r90 top
R9 "3.6K/0805" 0805R 434.003,-102.399 r90 top
R9 "3.6K/0805" 0805R 293.003,-102.399 r90 top
R10 "NC" 0805R 449.791,334.196 r90 top
R10 "NC" 0805R 308.791,334.196 r90 top
R10 "NC" 0805R 436.162,-102.399 r90 top
R10 "NC" 0805R 295.162,-102.399 r90 top
R11 "1.8R/0805" 0805R 445.219,334.196 r90 top
R11 "1.8R/0805" 0805R 304.219,334.196 r90 top
R11 "1.8R/0805" 0805R 431.59,-102.399 r90 top
R11 "1.8R/0805" 0805R 290.59,-102.399 r90 top
R12 "1.8R/0805" 0805R 443.06,334.196 r90 top
R12 "1.8R/0805" 0805R 302.06,334.196 r90 top
R12 "1.8R/0805" 0805R 429.431,-102.399 r90 top
R12 "1.8R/0805" 0805R 288.431,-102.399 r90 top
R13 "20R/0603" 0603R 482.382,363.99 r0 top
R13 "20R/0603" 0603R 341.382,363.99 r0 top
R13 "20R/0603" 0603R 468.753,-72.605 r0 top
R13 "20R/0603" 0603R 327.753,-72.605 r0 top
R14 "100K/0603" 0603R 477.175,368.943 r0 top
R14 "100K/0603" 0603R 336.175,368.943 r0 top
R14 "100K/0603" 0603R 463.546,-67.652 r0 top
R14 "100K/0603" 0603R 322.546,-67.652 r0 top
R15 "51K/0603" 0603R 485.43,366.617 r270 top
R15 "51K/0603" 0603R 344.43,366.617 r270 top
R15 "51K/0603" 0603R 471.801,-69.979 r270 top
R15 "51K/0603" 0603R 330.801,-69.979 r270 top
R16 "39K/0603" 0603R 485.43,363.355 r270 top
R16 "39K/0603" 0603R 344.43,363.355 r270 top
R16 "39K/0603" 0603R 471.801,-73.24 r270 top
R16 "39K/0603" 0603R 330.801,-73.24 r270 top
R17 "100K/0603" 0603R 480.731,368.943 r180 top
R17 "100K/0603" 0603R 339.731,368.943 r180 top
R17 "100K/0603" 0603R 467.102,-67.652 r180 top
R17 "100K/0603" 0603R 326.102,-67.652 r180 top
R18 "12K/0603" 0603R 486.827,366.617 r90 top
R18 "12K/0603" 0603R 345.827,366.617 r90 top
R18 "12K/0603" 0603R 473.198,-69.979 r90 top
R18 "12K/0603" 0603R 332.198,-69.979 r90 top
R19 "100K/0603" 0603R 494.622,302.573 r90 top
R19 "100K/0603" 0603R 353.622,302.573 r90 top
R19 "100K/0603" 0603R 480.993,-134.022 r90 top
R19 "100K/0603" 0603R 339.993,-134.022 r90 top
R20 "33K/0603" 0603R 496.146,302.573 r270 top
R20 "33K/0603" 0603R 355.146,302.573 r270 top
R20 "33K/0603" 0603R 482.517,-134.022 r270 top
R20 "33K/0603" 0603R 341.517,-134.022 r270 top
R21 "100R/0603" 0603R 489.034,298.509 r0 top
R21 "100R/0603" 0603R 348.034,298.509 r0 top
R21 "100R/0603" 0603R 475.405,-138.086 r0 top
R21 "100R/0603" 0603R 334.405,-138.086 r0 top
R22 "1K/0603" 0603R 496.971,300.16 r180 top
R22 "1K/0603" 0603R 355.971,300.16 r180 top
R22 "1K/0603" 0603R 483.343,-136.435 r180 top
R22 "1K/0603" 0603R 342.343,-136.435 r180 top
R23 "100K/0603" 0603R 483.446,300.922 r270 top
R23 "100K/0603" 0603R 342.446,300.922 r270 top
R23 "100K/0603" 0603R 469.817,-135.673 r270 top
R23 "100K/0603" 0603R 328.817,-135.673 r270 top
R24 "10K/0603" 0603R 511.005,326.83 r180 top
R24 "10K/0603" 0603R 370.005,326.83 r180 top
R24 "10K/0603" 0603R 497.376,-109.765 r180 top
R24 "10K/0603" 0603R 356.376,-109.765 r180 top
R25 "10K/0603" 0603R 511.005,325.376 r0 top
R25 "10K/0603" 0603R 370.005,325.376 r0 top
R25 "10K/0603" 0603R 497.376,-111.219 r0 top
R25 "10K/0603" 0603R 356.376,-111.219 r0 top
R26 "430R/0603" 0603R 511.005,320.338 r180 top
R26 "430R/0603" 0603R 370.005,320.338 r180 top
R26 "430R/0603" 0603R 497.376,-116.257 r180 top
R26 "430R/0603" 0603R 356.376,-116.257 r180 top
R27 "10K/0603" 0603R 511.005,323.852 r180 top
R27 "10K/0603" 0603R 370.005,323.852 r180 top
R27 "10K/0603" 0603R 497.376,-112.743 r180 top
R27 "10K/0603" 0603R 356.376,-112.743 r180 top
R28 "0R/0603" 0603R 535.089,364.654 r0 top
R28 "0R/0603" 0603R 394.089,364.654 r0 top
R28 "0R/0603" 0603R 521.461,-71.942 r0 top
R28 "0R/0603" 0603R 380.461,-71.942 r0 top
R29 "10K/0603" 0603R 517.482,287.46 r270 top
R29 "10K/0603" 0603R 376.482,287.46 r270 top
R29 "10K/0603" 0603R 503.853,-149.135 r270 top
R29 "10K/0603" 0603R 362.853,-149.135 r270 top
R30 "10K/0603" 0603R 533.103,301.303 r0 top
R30 "10K/0603" 0603R 392.103,301.303 r0 top
R30 "10K/0603" 0603R 519.474,-135.292 r0 top
R30 "10K/0603" 0603R 378.474,-135.292 r0 top
R31 "430R/0603" 0603R 529.667,301.303 r0 top
R31 "430R/0603" 0603R 388.667,301.303 r0 top
R31 "430R/0603" 0603R 516.038,-135.292 r0 top
R31 "430R/0603" 0603R 375.038,-135.292 r0 top
R32 "NC" 0603R 525.991,296.477 r270 top
R32 "NC" 0603R 384.991,296.477 r270 top
R32 "NC" 0603R 512.362,-140.118 r270 top
R32 "NC" 0603R 371.362,-140.118 r270 top
R33 "1K/0603" 0603R 526.445,312.389 r90 top
R33 "1K/0603" 0603R 385.445,312.389 r90 top
R33 "1K/0603" 0603R 512.816,-124.206 r90 top
R33 "1K/0603" 0603R 371.816,-124.206 r90 top
R34 "10K/0603" 0603R 504.528,294.278 r90 top
R34 "10K/0603" 0603R 363.528,294.278 r90 top
R34 "10K/0603" 0603R 490.899,-142.318 r90 top
R34 "10K/0603" 0603R 349.899,-142.318 r90 top
R35 "430R/0603" 0603R 501.917,331.275 r180 top
R35 "430R/0603" 0603R 360.917,331.275 r180 top
R35 "430R/0603" 0603R 488.289,-105.32 r180 top
R35 "430R/0603" 0603R 347.289,-105.32 r180 top
R36 "10K/0603" 0603R 501.917,332.926 r180 top
R36 "10K/0603" 0603R 360.917,332.926 r180 top
R36 "10K/0603" 0603R 488.289,-103.669 r180 top
R36 "10K/0603" 0603R 347.289,-103.669 r180 top
R37 "430R/0603" 0603R 505.48,331.275 r180 top
R37 "430R/0603" 0603R 364.48,331.275 r180 top
R37 "430R/0603" 0603R 491.852,-105.32 r180 top
R37 "430R/0603" 0603R 350.852,-105.32 r180 top
R38 "430R/0603" 0603R 508.902,331.275 r180 top
R38 "430R/0603" 0603R 367.902,331.275 r180 top
R38 "430R/0603" 0603R 495.274,-105.32 r180 top
R38 "430R/0603" 0603R 354.274,-105.32 r180 top
R39 "10K/0603" 0603R 505.48,332.926 r180 top
R39 "10K/0603" 0603R 364.48,332.926 r180 top
R39 "10K/0603" 0603R 491.852,-103.669 r180 top
R39 "10K/0603" 0603R 350.852,-103.669 r180 top
R40 "10K/0603" 0603R 508.902,332.926 r180 top
R40 "10K/0603" 0603R 367.902,332.926 r180 top
R40 "10K/0603" 0603R 495.274,-103.669 r180 top
R40 "10K/0603" 0603R 354.274,-103.669 r180 top
R41 "10K/0603" 0603R 522.655,335.477 r180 top
R41 "10K/0603" 0603R 381.655,335.477 r180 top
R41 "10K/0603" 0603R 509.026,-101.118 r180 top
R41 "10K/0603" 0603R 368.026,-101.118 r180 top
R42 "10K/0603" 0603R 525.356,325.825 r270 top
R42 "10K/0603" 0603R 384.356,325.825 r270 top
R42 "10K/0603" 0603R 511.727,-110.77 r270 top
R42 "10K/0603" 0603R 370.727,-110.77 r270 top
R43 "10K/0603" 0603R 525.356,321.242 r270 top
R43 "10K/0603" 0603R 384.356,321.242 r270 top
R43 "10K/0603" 0603R 511.727,-115.353 r270 top
R43 "10K/0603" 0603R 370.727,-115.353 r270 top
R44 "10K/0603" 0603R 518.371,317.686 r0 top
R44 "10K/0603" 0603R 377.371,317.686 r0 top
R44 "10K/0603" 0603R 504.742,-118.909 r0 top
R44 "10K/0603" 0603R 363.742,-118.909 r0 top
R45 "220R/5%/1206" 1206R 519.895,328.989 r0 top
R45 "220R/5%/1206" 1206R 378.895,328.989 r0 top
R45 "220R/5%/1206" 1206R 506.266,-107.606 r0 top
R45 "220R/5%/1206" 1206R 365.266,-107.606 r0 top
R46 "10K/0603" 0603R 522.308,317.686 r180 top
R46 "10K/0603" 0603R 381.308,317.686 r180 top
R46 "10K/0603" 0603R 508.679,-118.909 r180 top
R46 "10K/0603" 0603R 367.679,-118.909 r180 top
R47 "10K/0603" 0603R 518.371,319.845 r180 top
R47 "10K/0603" 0603R 377.371,319.845 r180 top
R47 "10K/0603" 0603R 504.742,-116.75 r180 top
R47 "10K/0603" 0603R 363.742,-116.75 r180 top
R48 "220R/5%/1206" 1206R 513.799,328.989 r0 top
R48 "220R/5%/1206" 1206R 372.799,328.989 r0 top
R48 "220R/5%/1206" 1206R 500.17,-107.606 r0 top
R48 "220R/5%/1206" 1206R 359.17,-107.606 r0 top
R49 "1K/0603" 0603R 518.371,322.004 r0 top
R49 "1K/0603" 0603R 377.371,322.004 r0 top
R49 "1K/0603" 0603R 504.742,-114.591 r0 top
R49 "1K/0603" 0603R 363.742,-114.591 r0 top
R50 "10K/0603" 0603R 514.561,317.686 r0 top
R50 "10K/0603" 0603R 373.561,317.686 r0 top
R50 "10K/0603" 0603R 500.932,-118.909 r0 top
R50 "10K/0603" 0603R 359.932,-118.909 r0 top
R51 "10K/0603" 0603R 514.561,326.83 r180 top
R51 "10K/0603" 0603R 373.561,326.83 r180 top
R51 "10K/0603" 0603R 500.932,-109.765 r180 top
R51 "10K/0603" 0603R 359.932,-109.765 r180 top
R52 "1K/0603" 0603R 514.585,325.393 r180 top
R52 "1K/0603" 0603R 373.585,325.393 r180 top
R52 "1K/0603" 0603R 500.956,-111.202 r180 top
R52 "1K/0603" 0603R 359.956,-111.202 r180 top
R53 "10K/0603" 0603R 530.086,318.557 r270 top
R53 "10K/0603" 0603R 389.086,318.557 r270 top
R53 "10K/0603" 0603R 516.457,-118.039 r270 top
R53 "10K/0603" 0603R 375.457,-118.039 r270 top
R54 "10K/0603" 0603R 533.183,318.557 r270 top
R54 "10K/0603" 0603R 392.183,318.557 r270 top
R54 "10K/0603" 0603R 519.554,-118.039 r270 top
R54 "10K/0603" 0603R 378.554,-118.039 r270 top
R55 "10K/0603" 0603R 530.975,331.029 r0 top
R55 "10K/0603" 0603R 389.975,331.029 r0 top
R55 "10K/0603" 0603R 517.346,-105.567 r0 top
R55 "10K/0603" 0603R 376.346,-105.567 r0 top
R56 "10R/5%/1206" 1206R 522.909,338.398 r180 top
R56 "10R/5%/1206" 1206R 381.909,338.398 r180 top
R56 "10R/5%/1206" 1206R 509.28,-98.197 r180 top
R56 "10R/5%/1206" 1206R 368.28,-98.197 r180 top
R57 "100R/0603" 0603R 534.731,318.557 r270 top
R57 "100R/0603" 0603R 393.731,318.557 r270 top
R57 "100R/0603" 0603R 521.103,-118.039 r270 top
R57 "100R/0603" 0603R 380.103,-118.039 r270 top
R58 "10R/5%/1206" 1206R 522.909,340.938 r180 top
R58 "10R/5%/1206" 1206R 381.909,340.938 r180 top
R58 "10R/5%/1206" 1206R 509.28,-95.657 r180 top
R58 "10R/5%/1206" 1206R 368.28,-95.657 r180 top
R59 "10K/0603" 0603R 534.15,331.029 r0 top
R59 "10K/0603" 0603R 393.15,331.029 r0 top
R59 "10K/0603" 0603R 520.521,-105.567 r0 top
R59 "10K/0603" 0603R 379.521,-105.567 r0 top
R60 "10K/0603" 0603R 531.634,318.557 r90 top
R60 "10K/0603" 0603R 390.634,318.557 r90 top
R60 "10K/0603" 0603R 518.006,-118.039 r90 top
R60 "10K/0603" 0603R 377.006,-118.039 r90 top
R61 "100R/0603" 0603R 528.243,321.242 r90 top
R61 "100R/0603" 0603R 387.243,321.242 r90 top
R61 "100R/0603" 0603R 514.614,-115.353 r90 top
R61 "100R/0603" 0603R 373.614,-115.353 r90 top
R62 "100R/0603" 0603R 526.846,321.242 r90 top
R62 "100R/0603" 0603R 385.846,321.242 r90 top
R62 "100R/0603" 0603R 513.217,-115.353 r90 top
R62 "100R/0603" 0603R 372.217,-115.353 r90 top
R69 "1K/0603" 0603R 501.607,300.16 r180 top
R69 "1K/0603" 0603R 360.607,300.16 r180 top
R69 "1K/0603" 0603R 487.978,-136.435 r180 top
R69 "1K/0603" 0603R 346.978,-136.435 r180 top
RF1 "100R/2W" FUSE/3.15A 452.424,272.104 r0 top
RF1 "100R/2W" FUSE/3.15A 311.424,272.104 r0 top
RF1 "100R/2W" FUSE/3.15A 438.795,-164.491 r0 top
RF1 "100R/2W" FUSE/3.15A 297.795,-164.491 r0 top
RXD1 "OTHER/TEST" TEST#2 501.099,298.763 r270 top
RXD1 "OTHER/TEST" TEST#2 360.099,298.763 r270 top
RXD1 "OTHER/TEST" TEST#2 487.47,-137.832 r270 top
RXD1 "OTHER/TEST" TEST#2 346.47,-137.832 r270 top
RY1 "TDK471KD14" RES/RY/TDK471KD14 443.28,272.612 r0 top
RY1 "TDK471KD14" RES/RY/TDK471KD14 302.28,272.612 r0 top
RY1 "TDK471KD14" RES/RY/TDK471KD14 429.651,-163.983 r0 top
RY1 "TDK471KD14" RES/RY/TDK471KD14 288.651,-163.983 r0 top
SW1 "船型开关" "DIP4 - DUPLICATE" 434.644,260.42 r270 top
SW1 "船型开关" "DIP4 - DUPLICATE" 293.644,260.42 r270 top
SW1 "船型开关" "DIP4 - DUPLICATE" 421.015,-176.175 r270 top
SW1 "船型开关" "DIP4 - DUPLICATE" 280.015,-176.175 r270 top
T1 "OTHER/TEST" TEST#2 504.147,298.89 r180 top
T1 "OTHER/TEST" TEST#2 363.147,298.89 r180 top
T1 "OTHER/TEST" TEST#2 490.518,-137.705 r180 top
T1 "OTHER/TEST" TEST#2 349.518,-137.705 r180 top
TR1 "PN8370 24V 0.4A" "L/TRANS/DIP/PN8370 24V 0.4A" 438.234,346.769 r90 top
TR1 "PN8370 24V 0.4A" "L/TRANS/DIP/PN8370 24V 0.4A" 297.234,346.769 r90 top
TR1 "PN8370 24V 0.4A" "L/TRANS/DIP/PN8370 24V 0.4A" 424.605,-89.826 r90 top
TR1 "PN8370 24V 0.4A" "L/TRANS/DIP/PN8370 24V 0.4A" 283.605,-89.826 r90 top
TXD1 "OTHER/TEST" TEST#2 502.623,298.763 r270 top
TXD1 "OTHER/TEST" TEST#2 361.623,298.763 r270 top
TXD1 "OTHER/TEST" TEST#2 488.994,-137.832 r270 top
TXD1 "OTHER/TEST" TEST#2 347.994,-137.832 r270 top
U1 "PN8370" SOP-7 447.124,341.181 r180 top
U1 "PN8370" SOP-7 306.124,341.181 r180 top
U1 "PN8370" SOP-7 433.495,-95.414 r180 top
U1 "PN8370" SOP-7 292.495,-95.414 r180 top
U2 "MP9942/SOT23-8" TSOT-8 479.087,367.603 r0 top
U2 "MP9942/SOT23-8" TSOT-8 338.087,367.603 r0 top
U2 "MP9942/SOT23-8" TSOT-8 465.458,-68.992 r0 top
U2 "MP9942/SOT23-8" TSOT-8 324.458,-68.992 r0 top
U3 "LM358" SOIC-8 485.916,304.217 r0 top
U3 "LM358" SOIC-8 344.916,304.217 r0 top
U3 "LM358" SOIC-8 472.287,-132.378 r0 top
U3 "LM358" SOIC-8 331.287,-132.378 r0 top
U4 "LSD4RF-2F717N30" MODEL/LSD4RF-2F717N30 522.782,357.575 r270 top
U4 "LSD4RF-2F717N30" MODEL/LSD4RF-2F717N30 381.782,357.575 r270 top
U4 "LSD4RF-2F717N30" MODEL/LSD4RF-2F717N30 509.153,-79.02 r270 top
U4 "LSD4RF-2F717N30" MODEL/LSD4RF-2F717N30 368.153,-79.02 r270 top
U5 "STM32F030RCT6/LQFP64" LQFP64 521.108,295.087 r180 top locked
U5 "STM32F030RCT6/LQFP64" LQFP64 380.108,295.087 r180 top locked
U5 "STM32F030RCT6/LQFP64" LQFP64 507.479,-141.508 r180 top locked
U5 "STM32F030RCT6/LQFP64" LQFP64 366.479,-141.508 r180 top locked
U6 "M24512-RMN6TP" SOP-8 485.986,293.556 r0 top
U6 "M24512-RMN6TP" SOP-8 344.986,293.556 r0 top
U6 "M24512-RMN6TP" SOP-8 472.357,-143.039 r0 top
U6 "M24512-RMN6TP" SOP-8 331.357,-143.039 r0 top
U7 "ULN2003ADR" SOP-16 509.862,281.745 r270 top
U7 "ULN2003ADR" SOP-16 368.862,281.745 r270 top
U7 "ULN2003ADR" SOP-16 496.233,-154.85 r270 top
U7 "ULN2003ADR" SOP-16 355.233,-154.85 r270 top
U8 "ULN2003ADR" SOP-16 525.229,281.745 r270 top
U8 "ULN2003ADR" SOP-16 384.229,281.745 r270 top
U8 "ULN2003ADR" SOP-16 511.6,-154.85 r270 top
U8 "ULN2003ADR" SOP-16 370.6,-154.85 r270 top
U9 "SP3485" SOP-8 530.594,322.24 r90 top
U9 "SP3485" SOP-8 389.594,322.24 r90 top
U9 "SP3485" SOP-8 516.965,-114.356 r90 top
U9 "SP3485" SOP-8 375.965,-114.356 r90 top
U10 "SPX1117" SOT-223 489,336.112 r180 top
U10 "SPX1117" SOT-223 348,336.112 r180 top
U10 "SPX1117" SOT-223 475.371,-100.483 r180 top
U10 "SPX1117" SOT-223 334.371,-100.483 r180 top
XTAL1 "OSC 12MHZ" OSC/SMT/12M 527.999,297.693 r0 top
XTAL1 "OSC 12MHZ" OSC/SMT/12M 386.999,297.693 r0 top
XTAL1 "OSC 12MHZ" OSC/SMT/12M 514.37,-138.902 r0 top
XTAL1 "OSC 12MHZ" OSC/SMT/12M 373.37,-138.902 r0 top

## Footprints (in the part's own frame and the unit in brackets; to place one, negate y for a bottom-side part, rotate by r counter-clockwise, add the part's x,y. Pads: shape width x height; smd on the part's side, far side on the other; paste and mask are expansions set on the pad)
0603R [mil]
  rect 35x32 smd: 1(-32.5,0) 2(32.5,0)
  silkscreen extent -58,-25 58,25, body extent -33,-15 30,16, height 18
0805R [mm]
  rect 1.2x1.524 smd: 1(0,0) 2(2.3,0)
  silkscreen extent -1,-1.1 3.3,1.1, body extent 0.13,-0.64 2.13,0.62, height 0.55
1206R [mm]
  rect 1.5x1.5 smd: 1(-0.02,0) 2(3.409,0)
  silkscreen extent -1.29,-1.27 4.68,1.27, body extent 0.13,-0.76 3.33,0.84, height 0.6
BJT/SMT/SOT-23 [mm]
  rect 1.143x1.27 smd: 1(0,0) 2(1.95,0)
  rect 1.27x1.27 smd: 3(1,2.5)
  silkscreen extent -0.78,-0.8 2.78,3.26
CAP/DIP/0.1uF/250V [mil]
  round 79 hole 39: 1(-399,0) 2(0,0)
  silkscreen extent -472,-118 79,118
CAP/DIP/6.8UF/400V/10MM [mm]
  oval 2x1.6 hole 1: 1(0,-2.5) 2(0,2.5)
  silkscreen extent -4.95,-5.02 5.13,4.98
CAP/DIP/10uF/50V [mm]
  oval 1x1.5 hole 0.7: 1(0,0) 2(2,0)
  silkscreen extent -1.5,-2.5 3.5,2.5
CAP/DIP/102M/250V [mm]
  round 1.5 hole 0.8: 1(0,0) 2(10,0)
  silkscreen extent -1.3,-1.29 11.46,1.31
CAP/SMT/100UF/25V [mm]
  rect 2x2 smd: 1(-0.325,-0.127) 2(6.675,-0.127)
  silkscreen extent -0.1,-3.49 6.3,2.91
CAP/SMT/220UF/16V [mm]
  rect 3.3x1.7 smd: 1(-2.789,0.007) 2(2.811,0.007)
  silkscreen extent -4.06,-3.29 3.31,3.31
CAP/SMT/220UF/50V [mm]
  rect 3.3x1.7 smd: 1(0,-5) 2(10.3,-5)
  silkscreen extent -1.27,-10.2 10.08,-0.21
CAP/SMT/330UF/6.3V [mm]
  rect 2x2 smd: 1(0.056,0) 2(7.056,0)
  silkscreen extent 0.28,-3.37 6.68,3.03
CAP/SMT/0603C [mil]
  rect 35x32 smd: 1(-1,1.97) 2(64,1.97)
  silkscreen extent -28,-24 89,30, body extent -20,-20 82,19, height 35
CAP/SMT/0805C [mm]
  rect 1.2x1.524 smd: 1(0.01,0.01) 2(2.296,0.01)
  silkscreen extent -0.99,-1.13 3.32,1.15, body extent -0.38,-0.64 2.62,0.76, height 0.93
CAP/SMT/1206C [mm]
  rect 1.5x1.5 smd: 1(0.026,0.025) 2(3.455,0.025)
  silkscreen extent -1.25,-1.24 4.73,1.3, body extent -0.38,-0.89 3.82,0.91, height 0.95
CAP/SMT/TAJC476M010RNJ [mm]
  rect 2x3.5 smd: 1(0.047,-0.183)
  oct 2x3.5 smd: 2(5.647,-0.183)
  silkscreen extent -1.25,-2.18 6.95,1.82, body extent -0.13,-1.78 5.87,1.42, height 2.6
CON/DIP/1×3PIN/5.0MM/WJ103-3P [mm]
  round 2.5 hole 1.6: 1(-5,0)
  round 2.5 hole 1.3: 2(0,0) 3(5,0)
  silkscreen extent -7.5,-7.3 8.1,6.1
CON/DIP/1×5PIN/2.0MM [mm]
  rect 1.575x1.575 hole 0.8 mask+0.102: 1(0,0)
  round 1.575 hole 0.8 mask+0.102: 2(2,0) 3(4,0) 4(6,0)
  oval 1.2x1.5 hole 0.8 mask+0.102: 5(8,0)
  silkscreen extent -1.27,-1.27 9.14,1.27
CON/DIP/1×6PIN/5.0MM/WJ103-6P [mm]
  round 2.5 hole 1.3: 1(-12.5,0) 2(-7.5,0) 3(-2.5,0) 4(2.5,0) 5(7.5,0) 6(12.5,0)
  silkscreen extent -15,-7.3 15.6,6.1
CON/DIP/1×18PIN/5.0MM/WJ103-18P [mm]
  round 2.5 hole 1.6: 1(-40,0)
  round 2.5 hole 1.3: 2(-35,0) 3(-30,0) 4(-25,0) 5(-20,0) 6(-15,0) 7(-10,0) 8(-5,0) 9(0,0) 10(5,0) 11(10,0) 12(15,0) 13(20,0) 14(25,0) 15(30,0) 16(35,0) 17(40,0) 18(45,0)
  silkscreen extent -42.5,-7.3 48.1,6.1
CON/DIP/2X15PIN/2.54MM [mil]
  round 60 hole 35.43: 1(0,0) 2(100,0) 3(0,-100) 4(100,-100) 5(0,-200) 6(100,-200) 7(0,-300) 8(100,-300) 9(0,-400) 10(100,-400) 20(100,-900) 21(0,-1000) 22(100,-1000) 23(0,-1100) 24(100,-1100) 25(0,-1200) 26(100,-1200) 27(0,-1300) 28(100,-1300) 29(0,-1400) 30(100,-1400)
  oval 60x39.37 hole 35.43: 11(0,-500) 12(100,-500) 13(0,-600) 14(100,-600) 15(0,-700) 16(100,-700) 17(0,-800) 18(100,-800) 19(0,-900)
  silkscreen extent -65,-1470 170,100
D/SMT/DO-214AC [mil]
  rect 94.49x100 smd: 1(-187.98,-2) 2(1,-2)
  silkscreen extent -274,-65 56,61, body extent -190,-55 15,47, height 40
D/SMT/LED/0805 [mil]
  rect 50x60 smd: 1(2,-6) 2(92,-6)
  silkscreen extent -28,-46 178,34
D/SMT/MD6S-TR [mm]
  oval 3x1.2 smd: 1(-2.745,1.252) 2(-2.745,-1.248) 3(2.455,-1.248) 4(2.455,1.252)
  silkscreen extent -4.37,-4.29 4.24,3.61, body extent -3.44,-2.54 3.56,2.36, height 2.9
D/SMT/SMBJ4.0A [mil]
  rect 70x100 smd: 1(-4.72,-10) 2(200,-10)
  silkscreen extent -4,-96 232,70
D/SMT/SOD123 [mm]
  rect 2x1.8 smd: 1(0.229,0) 2(4.597,0)
  silkscreen extent -1.4,-1.14 5.84,1.14, body extent 0.51,-0.76 4.21,0.84, height 1.2
D/SMT/SOD-123 [mm]
  rect 1.6x1.2 smd: 1(-1.8,0) 2(1.8,0)
  silkscreen extent -3.43,-0.9 2.78,0.9, body extent -1.91,-0.76 1.79,0.84, height 1.2
"DIP4 - DUPLICATE" [mm]
  oval 7.5x2.5 hole 1.1 slot 6.5 at 0 deg: 2(0,10.5) 4(10.5,10.5) ""(0,0) ""(10.5,0)
  silkscreen extent -7.37,-5.08 17.63,25.92
FUSE/3.15A [mm]
  round 1.8 hole 1.1: 1(0,0) 2(5.08,0)
  silkscreen extent -1.71,-2 6.79,2
L/DIP/1mH [mm]
  round 1.5 hole 0.9: 1(0,0) 2(3,0)
  silkscreen extent -1.5,-3 4.5,3
L/DIP/20mH/UU9.8 [mm]
  rect 2x2 hole 0.85: 1(0,0)
  round 2 hole 0.85: 2(0,-7) 3(8,-7) 4(8,0)
  silkscreen extent -4.25,-9 12.25,2
L/DIP/500uH [mm]
  round 2 hole 0.9: 1(0,-4.875) 2(7.55,-4.85) 3(7.55,0) 4(0,0)
  silkscreen extent -2.08,-6.16 9.92,1.34
L/SMT/0603L [mil]
  rect 35x32 smd: 1(-1,-1) 2(64,-1)
  silkscreen extent -28,-26 91,24
L/SMT/SWPA3015S150MT [mm]
  rect 1.5x3 smd: 1(0.175,0.051) 2(3.175,0.051)
  silkscreen extent 0.25,-1.91 3.17,2.03
"L/TRANS/DIP/PN8370 24V 0.4A" [mm]
  round 1.6 hole 0.8: 1(0,0) 3(0,-6) 4(0,-9) 5(0,-12) 8(14,-6) 10(14,0)
  silkscreen extent -1.95,-14.22 16.26,1.65
LQFP64 [mm]
  rect 1.55x0.22 smd: 1(-0.193,0.013) 2(-0.193,-0.487) 3(-0.193,-0.987) 4(-0.193,-1.487) 5(-0.193,-1.987) 6(-0.193,-2.487) 7(-0.193,-2.987) 8(-0.193,-3.487) 9(-0.193,-3.987) 10(-0.193,-4.487) 11(-0.193,-4.987) 12(-0.193,-5.487) 13(-0.193,-5.987) 14(-0.193,-6.487) 15(-0.193,-6.987) 16(-0.193,-7.487) 33(12.107,-7.487) 34(12.107,-6.987) 35(12.107,-6.487) 36(12.107,-5.987) 37(12.107,-5.487) 38(12.107,-4.987) 39(12.107,-4.487) 40(12.107,-3.987) 41(12.107,-3.487) 42(12.107,-2.987) 43(12.107,-2.487) 44(12.107,-1.987) 45(12.107,-1.487) 46(12.107,-0.987) 47(12.107,-0.487) 48(12.107,0.013)
  rect 0.22x1.55 smd: 17(2.207,-9.887) 18(2.707,-9.887) 19(3.207,-9.887) 20(3.707,-9.887) 21(4.207,-9.887) 22(4.707,-9.887) 23(5.207,-9.887) 24(5.707,-9.887) 25(6.207,-9.887) 26(6.707,-9.887) 27(7.207,-9.887) 28(7.707,-9.887) 29(8.207,-9.887) 30(8.707,-9.887) 31(9.207,-9.887) 32(9.707,-9.887) 49(9.707,2.413) 50(9.207,2.413) 51(8.707,2.413) 52(8.207,2.413) 53(7.707,2.413) 54(7.207,2.413) 55(6.707,2.413) 56(6.207,2.413) 57(5.707,2.413) 58(5.207,2.413) 59(4.707,2.413) 60(4.207,2.413) 61(3.707,2.413) 62(3.207,2.413) 63(2.707,2.413) 64(2.207,2.413)
  silkscreen extent 0.16,-8.5 10.7,2.04
MODEL/LSD4RF-2F717N30 [mm]
  rect 1x1.9 smd: 1(-6.89,-8.85) 2(-4.89,-8.85) 3(-2.89,-8.85) 4(-0.89,-8.85) 5(1.11,-8.85) 6(3.11,-8.85) 7(5.11,-8.85) 8(7.11,-8.85) 9(7.11,8.85) 10(5.11,8.85) 11(3.11,8.85) 12(1.11,8.85) 13(-5.11,8.85) 14(-7.11,8.85)
  silkscreen extent -9.82,-9.2 9.21,9.6
OSC/SMT/12M [mm]
  rect 1.15x1.4 smd: 1(0,0) 2(0,-2.5) 3(2,-2.5) 4(2,0)
  silkscreen extent -1.52,-3.43 2.92,1.02
RELAY/HF46F-012-HSIT [mm] "LWH(20.5*7* 15.3MM)"
  oval 1.8x2.5 hole 1.092: 1(-4.7,-18.5) 2(-4.7,-11.5) 3(0,0) 4(-4.7,0)
  silkscreen extent -5.8,-19.8 1.23,1.2
RES/RY/TDK471KD14 [mm]
  oval 2x2.5 hole 1.1: 1(-3.7,0.584) 2(3.701,-0.583)
  silkscreen extent -7.35,-3.33 6.7,3.23
SMA [mm]
  round 3 hole 1.7: 1(-2.54,2.54) 2(2.54,2.54) 3(-2.54,-2.54) 4(2.54,-2.54)
  round 2.8 hole 1.5: 5(0,0)
  silkscreen extent -4.32,-4.32 4.32,4.32
SOIC-8 [mil]
  oval 100x24 smd: 1(0.27,-0.17) 2(0.27,-50.17) 3(0.27,-100.17) 4(0.27,-150.17) 5(240.27,-150.17) 6(240.27,-100.17) 7(240.27,-50.17) 8(240.27,-0.17)
  silkscreen extent 60,-180 180,20, body extent 5,-170 241,23, height 67
SOP-7 [mil]
  oval 100x24 smd: 1(-104.73,94.83) 2(-104.73,44.83) 3(-104.73,-5.17) 4(-104.73,-55.17) 5(135.27,-55.17) 6(135.27,-5.17) 7(135.27,94.83)
  silkscreen extent -45,-85 75,115, body extent -105,-75 131,118, height 67
SOP-8 [mil]
  oval 100x24 smd: 1(0.27,-0.17) 2(0.27,-50.17) 3(0.27,-100.17) 4(0.27,-150.17) 5(240.27,-150.17) 6(240.27,-100.17) 7(240.27,-50.17) 8(240.27,-0.17)
  silkscreen extent 60,-180 180,20
SOP-16 [mm]
  oval 2.2x0.7 smd: 1(0,0) 2(0,-1.27) 3(0,-2.54) 4(0,-3.81) 5(0,-5.08) 6(0,-6.35) 7(0,-7.62) 8(0,-8.89) 9(5.588,-8.89) 10(5.588,-7.62) 11(5.588,-6.35) 12(5.588,-5.08) 13(5.588,-3.81) 14(5.588,-2.54) 15(5.588,-1.27) 16(5.588,0)
  silkscreen extent 1.52,-9.53 4.06,0.64
SOT-223 [mm]
  rect 1.1x2.15 smd: 1(-0.005,-0.002) 2(2.295,-0.002) 3(4.595,-0.002)
  rect 3.5x2.15 smd: 2(2.145,6.798)
  silkscreen extent -1.05,-1.58 5.65,8.37, body extent -0.89,-0.13 5.61,6.83, height 1.7
TEST#1 [mm]
  round 1.5 smd: 1(0,0)
  silkscreen extent -1,-1 1,1
TEST#2 [mm]
  round 1 smd: 1(0,0)
  silkscreen extent -0.65,-0.65 0.65,0.65
TSOT-8 [mm]
  rect 1.2x0.4 smd: 1(0,0) 2(0,-0.65) 3(0,-1.3) 4(0,-1.95) 5(2.746,-1.95) 6(2.746,-1.3) 7(2.746,-0.65) 8(2.746,0)
  silkscreen extent 0.64,-2.41 2.03,0.51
